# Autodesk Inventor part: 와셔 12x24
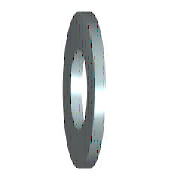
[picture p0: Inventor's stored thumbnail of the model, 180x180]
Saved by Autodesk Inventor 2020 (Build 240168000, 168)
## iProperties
IsCustomPart: 1
Created: 2012-02
Part Number: 와셔 12x24
Material: 스테인리스강
Description: 평면 와셔
Document SubType Name: Modeling
Standard: KS B 1326
Designer: mduedu
Standards Organization: KS
Language: ko-KR
Size Designation: 12x24
Categories: <MemberInstance><Categories><Category DisplayName="조임쇠" InternalName="e4da775c-781d-43d5-af7c-5136215cf5a6" Mnemonic="FSTN"><Category DisplayName="와셔" InternalN
Density: 1 g/cm^3
Appearance: 파란색 - 벽 페인트 - 광택
Author: mduedu
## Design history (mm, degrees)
sketch "스케치"
  geometry: C1 r 12 at (0, 0); C2 r 6.5 at (0, 0); 1 further point
  constraints: 2 centre point, 2 coincident
  dimensions: "d0" = 13 diameter of C2 (= SD1); "d1" = 24 diameter of C1 (= SD2)
extrude "본체" new body sketch "스케치" distance "d2" = 2.5 (= SD); taper "d3" = 0 deg
workaxis "Work Axis1"
workplane "Work Plane1"
body "Solid1"
other parameters: "SD1" = 13 [user parameter; used in 1 equation term], "SD2" = 24 [user parameter; used in 1 equation term], "SD" = 2.5 [user parameter; used in 1 equation term], "d4" = 0, "d5" = 0, "d6" = 0, "d7" = 0, "NND" = 12 [user parameter]
